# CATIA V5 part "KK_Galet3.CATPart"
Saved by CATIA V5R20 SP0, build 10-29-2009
Part number: Galet3
Bounding box of the stored display mesh (mm): x 9 to 13.5, y 222.003 to 241.997, z 5.003 to 24.997
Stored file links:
  G:\Khaled_CFAO_2011\ST2M\ST2M_GR2\aandujar\Khaled\CAD_thinkMOTION\KK_Galet3.CATPart
  G:\Khaled_CFAO_2011\ST2M\ST2M_GR2\aandujar\Khaled\CAD_thinkMOTION\KK_Aandujar.CATProduct
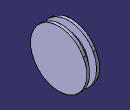
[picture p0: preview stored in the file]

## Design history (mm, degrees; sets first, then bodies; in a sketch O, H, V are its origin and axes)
WSupportSet1: ActiveGrid {3dwsupport RefPoint {point stored without definition}, 3DWOS ({wsupport Support xy-plane, RefPoint {3dwsupport}, GridIn {cartgrid Value 100, Stepbid1 0, Value 100, Stepbid2 0, Direction (1, 0, 0)}, GeometricData ({line type PtDir, Direction (1, 0, 0), Support xy-plane}; {line type PtDir, Direction (0, 1, 0), Support yz-plane})}; {wsupport Support yz-plane, RefPoint {3dwsupport}, GridIn {cartgrid Value 100, Stepbid1 0, Value 100, Stepbid2 0, Direction (0, 1, 0)}, GeometricData ({line type PtDir, Direction (0, 1, 0), Support yz-plane}; {line type PtDir, Direction (0, 0, 1), Support zx-plane})}; {wsupport Support zx-plane, RefPoint {3dwsupport}, GridIn {cartgrid Value 100, Stepbid1 0, Value 100, Stepbid2 0, Direction (0, 0, 1)}, GeometricData ({line type PtDir, Direction (0, 0, 1), Support zx-plane}; {line type PtDir, Direction (1, 0, 0), Support xy-plane})}), GeometricData ({line type PtDir, RefPoint {point stored without definition}, Direction (1, 0, 0), Support xy-plane}; {line type PtDir, RefPoint {point stored without definition}, Direction (0, 1, 0), Support yz-plane}; {line type PtDir, RefPoint {point stored without definition}, Direction (0, 0, 1), Support zx-plane})}
Set1
  Plane1: stored without definition
  Sketch1 on Plane1, origin (0, 0, 15), H (1, 0, 0), V (0, 1, 0)
    line L1 (9, 232) -> (13.5, 232)
    line L2 (13.5, 232) -> (13.5, 222)
    line L3 (13.5, 222) -> (12.5, 222)
    line L4 (12.5, 222) -> (12.5, 225)
    line L5 (12.5, 225) -> (10, 225)
    line L6 (10, 225) -> (10, 222)
    line L7 (10, 222) -> (9, 222)
    line L8 (9, 222) -> (9, 232)
    reference intersected line E1 through (12.5, 0) direction (0, 1) from Plane2
    reference projected line E2 (-7.5, 232) -> (32.5, 232) from Line1
    distance L2 L4 = 1
    distance L6 L8 = 1
    distance L4 L6 = 2.5
    distance L1 L5 = 7
    distance L1 L3 = 10
    horizontal: L1 H, L3 H, L5 H, L7 H
    vertical: L2 V, L4 V, L6 V, L8 V
    coincidence: L3 L7, L4 E1, L1 E2
Set2
  Plane2 "Plan.Ref5": linked copy from another document
  Line1 "Axe_pivot_galet3": linked copy from another document
Body1 (main body)
  Shaft1: profile Sketch1, axis Line1, angle 360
